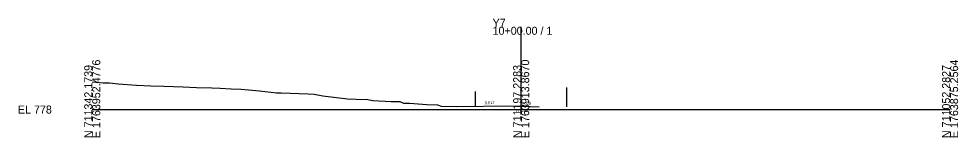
# Model space of a CAD drawing. Extents: x -26 to 2903, y -10 to 1056.
# Drawn here: x -25.7 to 302.8, y -9.7 to 31.8 of the extents above; entities that cross this region are included whole.
import ezdxf

# ---------------------------------------------------------------- set-up
doc = ezdxf.new("R2010")
doc.units = 0
for name, color, linetype in [('Default', 7, 'Continuous'), ('Exist Cross Section Cell', 7, 'Continuous'), ('Exist XS Center Line Elevation Label', 7, 'Continuous'), ('Exist XS Ground Line', 7, 'Continuous'), ('Scratch_Level_1', 7, 'Continuous')]:
    doc.layers.add(name, color=color, linetype=linetype)

msp = doc.modelspace()

# ---------------------------------------------------------------- linework, layer by layer
at = {"layer": 'Exist Cross Section Cell'}
for p, q in [((150, 0), (150, 28.98)), ((0, 0), (150, 0)), ((150, 0), (300, 0))]:
    msp.add_line(p, q, dxfattribs=at)
at = {"layer": 'Exist XS Ground Line'}
msp.add_lwpolyline([(0, 9.66), (3.82, 9.3), (6.02, 9.32), (9.09, 9.03), (15.53, 8.5), (20.45, 8.33), (25.03, 8.13), (31.81, 7.97), (36.51, 7.74), (41.86, 7.56), (44.68, 7.53), (48.57, 7.28), (52.11, 7.14), (58.52, 6.59), (64.41, 5.9), (66.08, 5.9), (75.55, 5.52), (77.65, 5.34), (80.66, 4.82), (89.22, 3.76), (92.24, 3.61), (96.42, 3.47), (98.14, 3.18), (104.59, 2.87), (107.61, 2.85), (108.84, 2.26), (110.95, 2.27), (116.97, 1.82), (120.69, 1.61), (121.97, 1.23), (127.51, 1.03), (146.01, 1.35), (150, 1.19), (156.24, 0.96)], dxfattribs=at)
at = {"layer": 'Scratch_Level_1'}
for p, q in [((166, 1), (166, 7.69)), ((134, 1), (134, 6.28)), ((127.51, 1.03), (146.01, 1.35)), ((146.01, 1.35), (156.24, 0.96))]:
    msp.add_line(p, q, dxfattribs=at)

# ---------------------------------------------------------------- texts
at = {"layer": 'Default'}
msp.add_text('-', height=0.0001, dxfattribs=at).set_placement((0, 0))
at = {"layer": 'Exist Cross Section Cell'}
for s, p in [('Y7', (140, 28.98)), ('10+00.00 / 1', (140, 26.18)), ('EL 778', (-26, -1.4))]:
    msp.add_text(s, height=2.8, dxfattribs=at).set_placement(p)
for s, p in [('E 1763952.4776', (2.8, -10)), ('E 1763913.8670', (152.8, -10)), ('E 1763875.2564', (302.8, -10)), ('N 711342.1739', (0, -10)), ('N 711197.2283', (150, -10)), ('N 711052.2827', (300, -10))]:
    msp.add_text(s, height=2.8, rotation=90, dxfattribs=at).set_placement(p)
at = {"layer": 'Exist XS Center Line Elevation Label'}
msp.add_text('779.19', height=1, dxfattribs=at).set_placement((147.99, -0.81))
at = {"layer": 'Scratch_Level_1'}
for s, rotation, p in [('0.017', 0.9663, (137.24, 1.85)), ('0.038', 357.8206, (150.02, 1.81))]:
    msp.add_text(s, height=1, rotation=rotation, dxfattribs=at).set_placement(p)

doc.saveas('drawing.dxf')
